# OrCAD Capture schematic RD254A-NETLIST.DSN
size A3
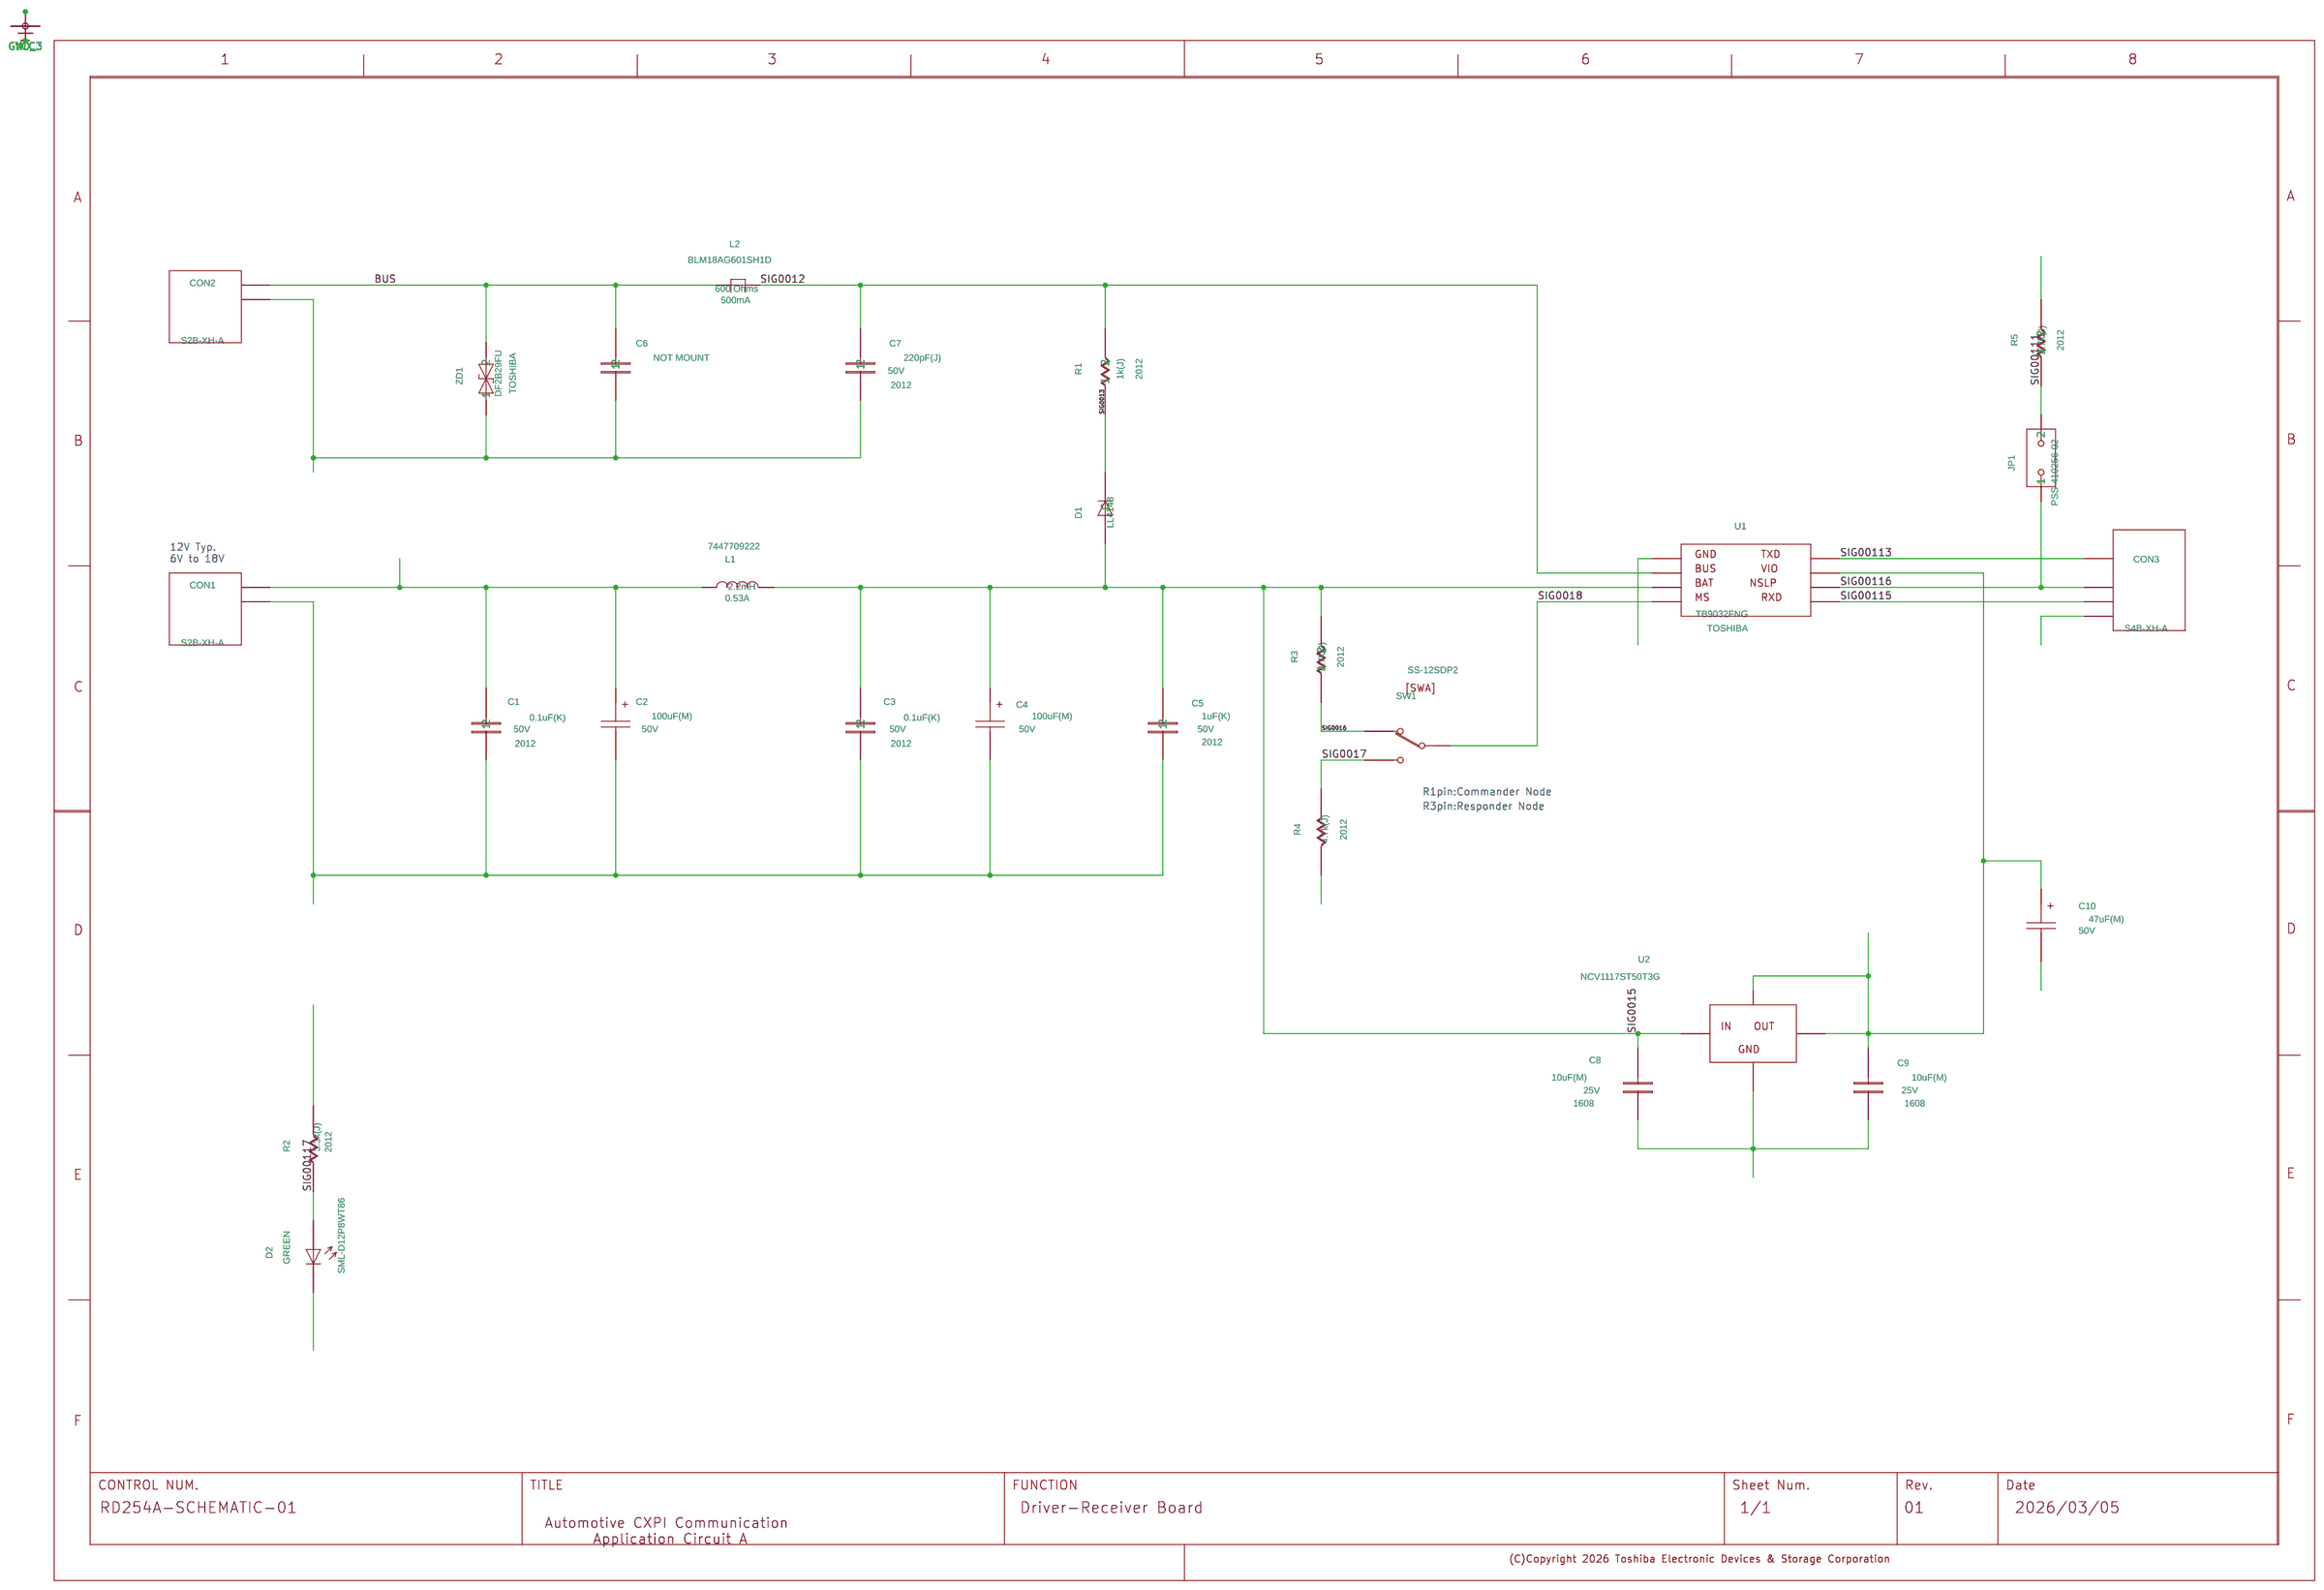
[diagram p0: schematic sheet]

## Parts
C1  C
C2  CP
C3  C
C4  CP
C5  C
C6  C
C7  C
C8  C
C9  C
C10  CP
CON1  S2B-XH-A
CON2  S2B-XH-A
CON3  S4B-XH-A
D1  D
D2  LED
JP1  PSS-410256-02
L1  L
L2  FB
R1  R
R2  R
R3  R
R4  R
R5  R
SW1  SWA
U1  TB9032FNG
U2  LD1117S50TR
U?#1  WAKU_DEF100
ZD1  ZDB

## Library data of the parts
C1 C3 = C: COMPONENTTYPE: 4; SAVECOUNT: 0; SIZECODESMD: 2012; VAL1: 0.1uF(K); VAL2: 50V
C2 C4 = CP: COMP: C; COMPONENTTYPE: 4; VAL1: 100uF(M); VAL2: 50V
C5 = C: COMPONENTTYPE: 4; SAVECOUNT: 0; SIZECODESMD: 2012; VAL1: 1uF(K); VAL2: 50V
C6 = C: COMPONENTTYPE: 4; NOTMOUNT: NOT MOUNT; SAVECOUNT: 0
C7 = C: COMPONENTTYPE: 4; SAVECOUNT: 0; SIZECODESMD: 2012; VAL1: 220pF(J); VAL2: 50V
C8 C9 = C#1: COMPONENTTYPE: 4; CaptureCellPackProp: C##1; SAVECOUNT: 0; SIZECODESMD: 1608; VAL1: 10uF(M); VAL2: 25V
C10 = CP: COMP: C; COMPONENTTYPE: 4; VAL1: 47uF(M); VAL2: 50V
CON1 CON2 = S2B-XH-A: COMPONENTTYPE: 4; SAVECOUNT: 18; UPDATETIME: 10:47:53
CON3 = S4B-XH-A: COMPONENTTYPE: 4
D1 = D: COMP: LL4148; COMPONENTTYPE: 4; VAL3: LL4148
D2 = LED: COMPONENTTYPE: 4; VAL2: GREEN; VAL3: SML-D12P8WT86
JP1 = PSS-410256-02: COMPONENTTYPE: 4
L1 = L: COMP: BLM18AG601SH1D; COMPONENTTYPE: 4; SAVECOUNT: 0; VAL1: 2.2mH; VAL2: 0.53A; VAL3: 7447709222
L2 = FB: COMP: BLM18AG601SH1D; COMPONENTTYPE: 4; SIZECODESMD: 1608; VAL1: 600 Ohms; VAL2: 500mA; VAL3: BLM18AG601SH1D
R1 = R: COMPONENTTYPE: 4; SAVECOUNT: 0; SIZECODESMD: 2012; VAL1: 1k(J); VAL2: 250mW
R2 = R#1: COMPONENTTYPE: 4; CaptureCellPackProp: R##1; SAVECOUNT: 0; SIZECODESMD: 2012; VAL1: 3.3k(J); VAL2: 250mW
R3 R5 = R: COMPONENTTYPE: 4; SAVECOUNT: 0; SIZECODESMD: 2012; VAL1: 4.7k(J); VAL2: 250mW
R4 = R#1: COMPONENTTYPE: 4; CaptureCellPackProp: R##1; SAVECOUNT: 0; SIZECODESMD: 2012; VAL1: 4.7k(J); VAL2: 250mW
SW1 = SWA: COMP: SS-12SDP2; COMPONENTTYPE: 4; SAVECOUNT: 0; VAL3: SS-12SDP2
U1 = TB9032FNG: COMPONENTTYPE: 4; USERCOMPTEXT3: TOSHIBA
U2 = LD1117S50TR: COMP: NCV1117DT50RKG; COMPONENTTYPE: 4; VAL3: NCV1117ST50T3G
U?#1 = WAKU_DEF100: COMPONENTTYPE: 2; DATE: 2026/03/05; DRAWINGNUMBER: RD254A-SCHEMATIC-01; FUNCTION: Driver-Receiver Board; REVISION: 01; SHEETNUMBER: 1/1; SHTSAVECOUNT: 36; TITLE: Automotive CXPI Communication / Application Circuit A; UPDATEDATE: 2026.3.12; UPDATETIME: 17:08:01
ZD1 = ZDB: COMP: DF2B29FU; COMPONENTTYPE: 4; USERCOMPTEXT3: TOSHIBA; VAL3: DF2B29FU

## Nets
GND: C1.2(1) C2.1 C3.2(1) C4.1 C5.2(1) C6.2(1) C7.2(1) C8.1 C9.1 C10.1 CON1.1 CON2.1 CON3.1 D2.C R4.2 U1.5 U2.1 ZD1.2(1)
VBAT: C1.1(2) C2.2 CON1.2 L1.1 R2.2
BUS: C6.1(2) CON2.2 L2.1 ZD1.1(2)
SIG0012: C7.1(2) L2.2 R1.1(2) U1.6
SIG0013: D1.K(C) R1.2(1)
SIG0015: C3.1(2) C4.2 C5.1(2) C8.2 D1.A L1.2 R3.1(2) U1.7 U2.3
SIG0016: R3.2(1) SW1.1
SIG0017: R4.1 SW1.3
SIG0018: SW1.2 U1.8
SIG00111: JP1.1(2) R5.2(1)
SIG00113: CON3.4 U1.4
SIG00115: CON3.2 U1.1
SIG00116: CON3.3 JP1.2(1) U1.2
SIG00117: D2.A R2.1
VP_5R0_A: C9.2 C10.2 R5.1(2) U1.3 U2.2 U2.TAB

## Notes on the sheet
- 12V Typ.
  6V to 18V
- R1pin:Commander Node
- R3pin:Responder Node
